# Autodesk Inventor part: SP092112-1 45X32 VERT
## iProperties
Created: 2012-09
Part Number: SP092112-1 45X32 VERT
Material: Aluminum-6061
Description: PROFILE 45X32 UL
Document SubType Name: Modeling
Designer: Administrator
Stock Number: 20.1065 PROFILE 45X32 UL
Density: 2.71 g/cm^3
FINISH: CLEAR ANODIZED
Author: Administrator
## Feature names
1. Extrusion1
